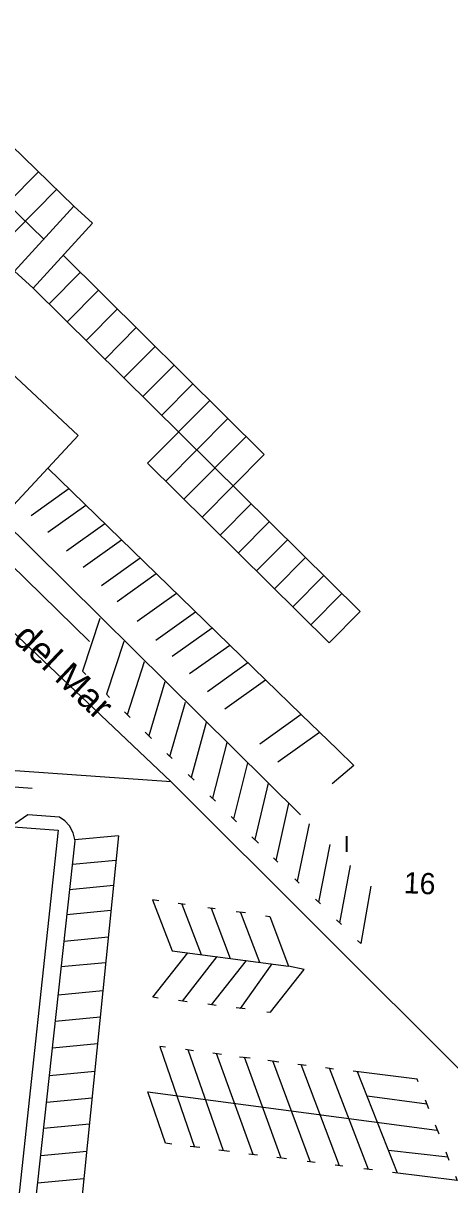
# Model space of a CAD drawing. Extents: x 282771 to 285132, y 4823109 to 4825496.
# Drawn here: x 283202.2 to 283242.3, y 4824434.6 to 4824543.9 of the extents above; entities that cross this region are included whole.
import ezdxf

# ---------------------------------------------------------------- set-up
doc = ezdxf.new("R2010")
doc.units = 0
for name, color, linetype in [('ACERA-BORDILLO', 7, 'Continuous'), ('ACERA-INTERIOR', 7, 'Continuous'), ('APARCAMIENTO', 7, 'Continuous'), ('CALLE-EJE', 7, 'Continuous'), ('CALLE-TEXTO', 7, 'Continuous'), ('EDIFICIO', 7, 'Continuous'), ('NUM-PORTAL', 7, 'Continuous'), ('SENAL-VIARIA', 7, 'Continuous'), ('TXT-ALTURA-EDIFICIO', 7, 'Continuous'), ('VALLA', 7, 'Continuous')]:
    doc.layers.add(name, color=color, linetype=linetype)

msp = doc.modelspace()

# ---------------------------------------------------------------- linework, layer by layer
at = {"layer": 'ACERA-BORDILLO'}
msp.add_lwpolyline([(283197.04, 4824468.59), (283195.77, 4824469.95), (283187.84, 4824470.59), (283137.03, 4824474.36), (283133.05, 4824439.67), (283132.89, 4824438.39), (283132.89, 4824437.7), (283133.16, 4824437.12), (283133.69, 4824436.82), (283134.35, 4824436.73), (283200.76, 4824429.91), (283201.73, 4824429.77), (283202.31, 4824429.76), (283202.76, 4824429.99), (283203.11, 4824430.56), (283207.08, 4824466.97), (283206.92, 4824467.71), (283206.57, 4824468.38), (283206.13, 4824468.84), (283205.62, 4824469.21), (283202.65, 4824469.41), (283201, 4824468.29)], dxfattribs=at)
at = {"layer": 'ACERA-INTERIOR'}
for points in [[(283203.15, 4824518.97), (283208.71, 4824525.09), (283206.96, 4824526.69), (283201.39, 4824520.56), (283203.15, 4824518.97)], [(283221.17, 4824479.39), (283225, 4824482.12), (283228.36, 4824478.85), (283224.45, 4824476.07)], [(283231.76, 4824475.55), (283233.3, 4824474.05), (283231.25, 4824472.32)]]:
    msp.add_lwpolyline(points, dxfattribs=at)
at = {"layer": 'APARCAMIENTO'}
for points in [[(283189.25, 4824543.89), (283206.96, 4824526.69)], [(283186.42, 4824540.79), (283204.14, 4824523.58)], [(283197.81, 4824524.04), (283203.63, 4824529.92)], [(283199.53, 4824522.37), (283205.35, 4824528.25)], [(283205.96, 4824522.06), (283224.87, 4824503.32), (283219.03, 4824497.43)], [(283204.64, 4824517.49), (283207.58, 4824520.46)], [(283203.15, 4824518.97), (283233.88, 4824488.55), (283230.97, 4824485.61), (283213.91, 4824502.49), (283219.75, 4824508.39)], [(283206.34, 4824515.8), (283209.28, 4824518.77)], [(283208.12, 4824514.04), (283211.06, 4824517.01)], [(283209.9, 4824512.28), (283212.83, 4824515.25)], [(283211.67, 4824510.53), (283214.61, 4824513.49)], [(283213.45, 4824508.77), (283216.39, 4824511.73)], [(283215.23, 4824507.01), (283218.16, 4824509.97)], [(283215.62, 4824500.8), (283221.46, 4824506.7)], [(283217.32, 4824499.12), (283223.16, 4824505.01)], [(283204.53, 4824502.03), (283225, 4824482.12)], [(283202.95, 4824497.58), (283206.51, 4824500.11)], [(283204.53, 4824496), (283208.11, 4824498.55)], [(283220.73, 4824495.74), (283223.65, 4824498.68)], [(283206.27, 4824494.26), (283209.88, 4824496.83)], [(283222.44, 4824494.05), (283225.35, 4824496.99)], [(283207.83, 4824492.71), (283211.46, 4824495.29)], [(283224.15, 4824492.36), (283227.06, 4824495.3)], [(283209.56, 4824490.98), (283213.22, 4824493.58)], [(283225.85, 4824490.68), (283228.76, 4824493.61)], [(283211.04, 4824489.5), (283214.72, 4824492.12)], [(283227.56, 4824488.99), (283230.47, 4824491.92)], [(283212.92, 4824487.62), (283216.63, 4824490.26)], [(283229.26, 4824487.3), (283232.17, 4824490.24)], [(283209.42, 4824487.9), (283207.79, 4824482.94), (283208.09, 4824482.63)], [(283214.69, 4824485.86), (283218.42, 4824488.52)], [(283216.22, 4824484.33), (283219.98, 4824487.01)], [(283211.66, 4824485.72), (283210.03, 4824480.77), (283210.33, 4824480.46)], [(283217.86, 4824482.7), (283221.64, 4824485.39)], [(283213.59, 4824483.82), (283211.99, 4824478.83)], [(283219.53, 4824481.03), (283223.34, 4824483.74)], [(283215.53, 4824481.92), (283214.01, 4824476.85)], [(283216.01, 4824474.9), (283217.47, 4824480.01)], [(283212.27, 4824478.56), (283211.72, 4824479.1)], [(283228.36, 4824478.85), (283231.76, 4824475.55)], [(283219.42, 4824478.11), (283218, 4824472.94)], [(283213.67, 4824477.19), (283214.28, 4824476.6)], [(283226.16, 4824474.41), (283230.07, 4824477.19)], [(283221.35, 4824476.21), (283220, 4824470.99)], [(283216.2, 4824474.71), (283215.71, 4824475.2)], [(283223.29, 4824474.3), (283221.99, 4824469.03)], [(283218.28, 4824472.67), (283217.73, 4824473.22)], [(283225.24, 4824472.39), (283223.98, 4824467.08)], [(283220.3, 4824470.69), (283219.77, 4824471.21)], [(283225.98, 4824465.12), (283227.18, 4824470.49)], [(283222.27, 4824468.76), (283221.75, 4824469.27)], [(283229.11, 4824468.57), (283227.97, 4824463.17)], [(283211.17, 4824467.45), (283207.06, 4824467.06)], [(283211.17, 4824467.45), (283211.17, 4824467.45), (283207.67, 4824432.7)], [(283224.33, 4824466.74), (283223.7, 4824467.36)], [(283231.04, 4824466.61), (283229.97, 4824461.21)], [(283210.93, 4824465.12), (283206.83, 4824464.73)], [(283226.15, 4824464.96), (283225.73, 4824465.37)], [(283232.97, 4824464.65), (283231.96, 4824459.26)], [(283210.69, 4824462.75), (283206.57, 4824462.36)], [(283228.16, 4824462.98), (283227.75, 4824463.39)], [(283234.91, 4824462.71), (283233.96, 4824457.31), (283233.66, 4824457.6)], [(283214.96, 4824461.32), (283214.36, 4824461.41), (283216.21, 4824456.63), (283227.16, 4824455.19)], [(283230.16, 4824461.03), (283229.68, 4824461.49)], [(283210.46, 4824460.41), (283206.32, 4824460.01)], [(283217.43, 4824460.97), (283216.79, 4824461.06)], [(283217.12, 4824461.02), (283218.94, 4824456.26)], [(283220.26, 4824460.58), (283219.56, 4824460.67)], [(283219.88, 4824460.63), (283221.68, 4824455.9)], [(283223.11, 4824460.18), (283222.23, 4824460.3)], [(283222.64, 4824460.24), (283224.42, 4824455.54)], [(283224.98, 4824459.91), (283225.4, 4824459.86), (283227.16, 4824455.19)], [(283232.14, 4824459.09), (283231.68, 4824459.54)], [(283210.21, 4824457.91), (283206.05, 4824457.51)], [(283214.9, 4824452.18), (283214.39, 4824452.25), (283217.69, 4824456.43)], [(283217.18, 4824451.89), (283220.45, 4824456.07)], [(283209.96, 4824455.5), (283205.78, 4824455.1)], [(283219.9, 4824451.55), (283223.19, 4824455.71)], [(283222.64, 4824451.2), (283225.62, 4824455.39)], [(283225.13, 4824450.89), (283225.46, 4824450.85), (283228.64, 4824454.87), (283227.16, 4824455.19)], [(283209.7, 4824452.86), (283205.49, 4824452.46)], [(283217.64, 4824451.83), (283216.82, 4824451.94)], [(283220.34, 4824451.49), (283219.56, 4824451.59)], [(283209.45, 4824450.38), (283205.22, 4824449.98)], [(283223.07, 4824451.15), (283222.23, 4824451.25)], [(283209.2, 4824447.86), (283204.95, 4824447.45)], [(283215.6, 4824447.55), (283215.04, 4824447.63), (283218.3, 4824438.16)], [(283218.22, 4824447.22), (283217.46, 4824447.32)], [(283221.03, 4824437.81), (283217.71, 4824447.29)], [(283220.85, 4824446.88), (283220.04, 4824446.99)], [(283223.82, 4824437.45), (283220.37, 4824446.95)], [(283222.55, 4824446.66), (283223.56, 4824446.54)], [(283226.48, 4824437.11), (283223.02, 4824446.61)], [(283225.22, 4824446.32), (283226.24, 4824446.19)], [(283229.21, 4824436.75), (283225.68, 4824446.27)], [(283228.03, 4824445.96), (283228.83, 4824445.86)], [(283208.94, 4824445.28), (283204.67, 4824444.87)], [(283231.94, 4824436.4), (283228.34, 4824445.93)], [(283230.62, 4824445.63), (283231.4, 4824445.53)], [(283234.67, 4824436.05), (283231, 4824445.59)], [(283239.34, 4824444.28), (283239.25, 4824444.54), (283233.24, 4824445.3)], [(283237.4, 4824435.7), (283233.66, 4824445.25)], [(283208.68, 4824442.75), (283204.39, 4824442.34)], [(283216.17, 4824438.44), (283215.58, 4824438.52), (283213.94, 4824443.36), (283241.11, 4824439.75)], [(283240.18, 4824442.18), (283234.55, 4824442.96)], [(283240.01, 4824442.61), (283240.33, 4824441.8)], [(283208.44, 4824440.3), (283204.12, 4824439.89)], [(283240.94, 4824440.25), (283241.28, 4824439.4)], [(283208.18, 4824437.75), (283203.85, 4824437.33)], [(283218.82, 4824438.1), (283217.91, 4824438.21)], [(283221.6, 4824437.74), (283220.59, 4824437.87)], [(283224.23, 4824437.4), (283223.42, 4824437.5)], [(283242.14, 4824437.22), (283236.55, 4824437.84)], [(283242.27, 4824436.9), (283241.97, 4824437.67)], [(283226.96, 4824437.04), (283226.06, 4824437.16)], [(283229.66, 4824436.69), (283228.92, 4824436.79)], [(283232.28, 4824436.36), (283231.55, 4824436.45)], [(283207.92, 4824435.16), (283203.56, 4824434.75)], [(283235.05, 4824436), (283234.24, 4824436.1)], [(283242.85, 4824435.43), (283243.02, 4824435.02), (283236.93, 4824435.76)]]:
    msp.add_lwpolyline(points, dxfattribs=at)
at = {"layer": 'CALLE-EJE'}
for points in [[(283157.81, 4824527.78), (283216.11, 4824472.53)], [(283216.11, 4824472.53), (283132.89, 4824478.39)], [(283216.11, 4824472.53), (283244, 4824444.7), (283253.6, 4824419.26)]]:
    msp.add_lwpolyline(points, dxfattribs=at)
at = {"layer": 'EDIFICIO'}
for points in [[(283163.37, 4824531.01), (283165.38, 4824531.04), (283175.2, 4824521.71), (283176.11, 4824522.67), (283192.47, 4824506.81), (283201.29, 4824498.56), (283207.38, 4824505.09), (283198.6, 4824513.29), (283199.49, 4824514.32), (283183.29, 4824530.08), (283181.62, 4824528.36), (283177.82, 4824532.09), (283179.38, 4824533.68), (283174.25, 4824538.72), (283169.49, 4824533.86), (283165.93, 4824537.36), (283163.37, 4824531.01)], [(283182.22, 4824469.72), (283182.12, 4824468.89), (283180.87, 4824468.91), (283180.82, 4824468.22), (283181.27, 4824468.12), (283181.1, 4824467.15), (283185.83, 4824466.76), (283186.02, 4824469.43), (283192.42, 4824468.94), (283205.5, 4824467.96), (283201.56, 4824431.47)]]:
    msp.add_lwpolyline(points, dxfattribs=at)
at = {"layer": 'SENAL-VIARIA'}
for points in [[(283193.75, 4824503.6), (283192.06, 4824501.75), (283208.44, 4824485.72)], [(283140.34, 4824476.62), (283203.06, 4824471.93)]]:
    msp.add_lwpolyline(points, dxfattribs=at)
at = {"layer": 'VALLA'}
msp.add_lwpolyline([(283193.75, 4824503.6), (283228.28, 4824469.41)], dxfattribs=at)

# ---------------------------------------------------------------- texts
at = {"layer": 'CALLE-TEXTO'}
msp.add_text('Travesía del Mar', height=2.5, rotation=316.5386, dxfattribs=at).set_placement((283191.01, 4824495.45))
at = {"layer": 'NUM-PORTAL'}
msp.add_text('16', height=2, rotation=357.3587, dxfattribs=at).set_placement((283237.96, 4824462.05))
at = {"layer": 'TXT-ALTURA-EDIFICIO'}
msp.add_text('I', height=1.5, rotation=0, dxfattribs=at).set_placement((283232.35, 4824465.92))

doc.saveas('drawing.dxf')
